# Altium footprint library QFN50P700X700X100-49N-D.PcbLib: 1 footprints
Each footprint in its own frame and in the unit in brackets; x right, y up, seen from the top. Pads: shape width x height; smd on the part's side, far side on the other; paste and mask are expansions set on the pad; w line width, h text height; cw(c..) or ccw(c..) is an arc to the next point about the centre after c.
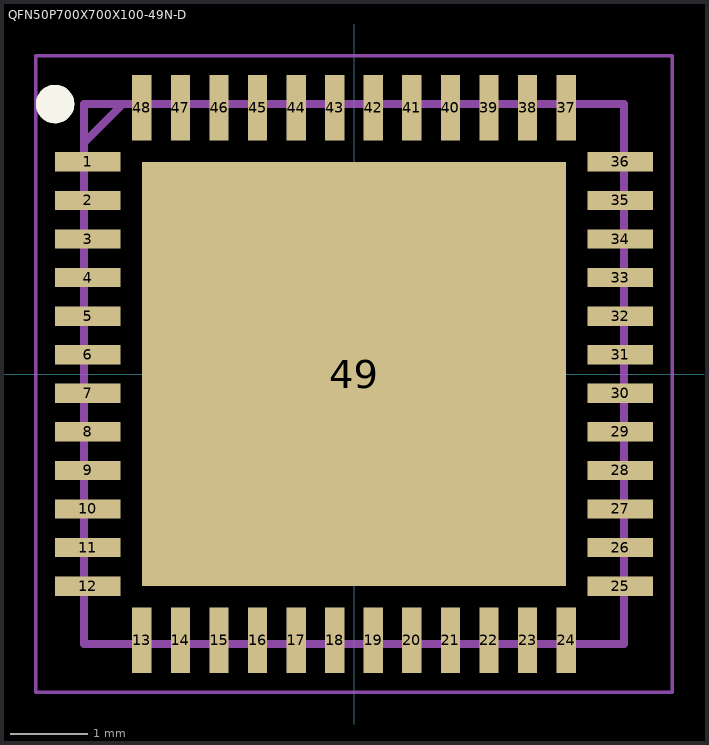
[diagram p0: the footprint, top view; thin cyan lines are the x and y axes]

## QFN50P700X700X100-49N-D [mm]
pads (49):
  rect 0.85x0.25 smd: 1(-3.45,2.75) 2(-3.45,2.25) 3(-3.45,1.75) 4(-3.45,1.25) 5(-3.45,0.75) 6(-3.45,0.25) 7(-3.45,-0.25) 8(-3.45,-0.75) 9(-3.45,-1.25) 10(-3.45,-1.75) 11(-3.45,-2.25) 12(-3.45,-2.75) 25(3.45,-2.75) 26(3.45,-2.25) 27(3.45,-1.75) 28(3.45,-1.25) 29(3.45,-0.75) 30(3.45,-0.25) 31(3.45,0.25) 32(3.45,0.75) 33(3.45,1.25) 34(3.45,1.75) 35(3.45,2.25) 36(3.45,2.75)
  rect 0.25x0.85 smd: 13(-2.75,-3.45) 14(-2.25,-3.45) 15(-1.75,-3.45) 16(-1.25,-3.45) 17(-0.75,-3.45) 18(-0.25,-3.45) 19(0.25,-3.45) 20(0.75,-3.45) 21(1.25,-3.45) 22(1.75,-3.45) 23(2.25,-3.45) 24(2.75,-3.45) 37(2.75,3.45) 38(2.25,3.45) 39(1.75,3.45) 40(1.25,3.45) 41(0.75,3.45) 42(0.25,3.45) 43(-0.25,3.45) 44(-0.75,3.45) 45(-1.25,3.45) 46(-1.75,3.45) 47(-2.25,3.45) 48(-2.75,3.45)
  rect 5.5x5.5 smd: 49(0,0)
Top Overlay:
  circle w0.25: c-3.875,3.5 r0.125
Mechanical 15:
  lines w0.1: -3.5,3 -3,3.5 ; -3.5,-3.5 3.5,-3.5 3.5,3.5 -3.5,3.5 -3.5,-3.5
Mechanical 20:
  lines w0.05: -4.125,-4.125 4.125,-4.125 4.125,4.125 -4.125,4.125 -4.125,-4.125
